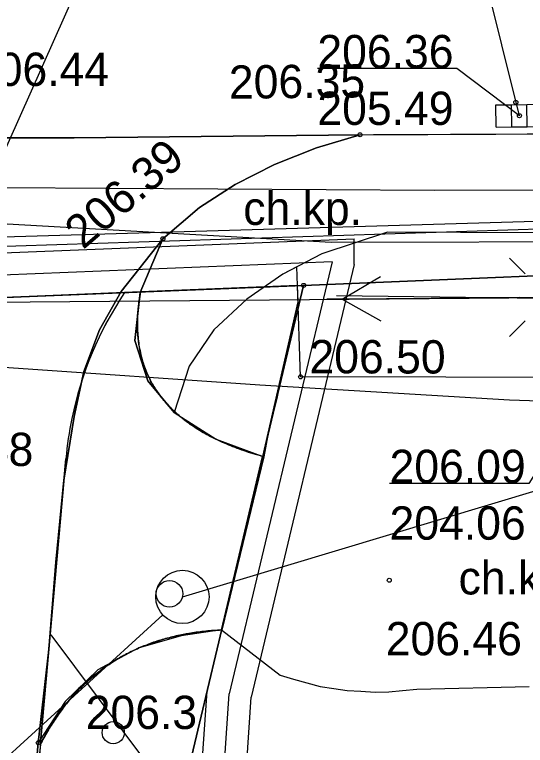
# Model space of a CAD drawing. Extents: x 6512606 to 6513347, y 6022524 to 6022728.
# Drawn here: x 6512739 to 6512750.51, y 6022662.97 to 6022679.43 of the extents above; entities that cross this region are included whole.
import ezdxf

# ---------------------------------------------------------------- set-up
doc = ezdxf.new("R2010")
doc.units = 0
for name, color, linetype in [('20', 7, 'Continuous'), ('203-punkt graniczny', 7, 'Continuous'), ('216-obręb ewidencyjny', 7, 'Continuous'), ('218-kontur użytku gruntowego', 7, 'Continuous'), ('219-działka ewidencyjna', 7, 'Continuous'), ('4', 7, 'Continuous'), ('chodnik', 7, 'Continuous'), ('chodnik (powierzchnia)', 7, 'Continuous'), ('chodnik (powierzchnia)-Atr17', 7, 'Continuous'), ('chodnik-Atr17', 7, 'Continuous'), ('Default', 7, 'Continuous'), ('inny obiekt zagospodarowania terenu', 7, 'Continuous'), ('jezdnia (powierzchnia)', 7, 'Continuous'), ('kolor_chodnik', 7, 'Continuous'), ('kolor_kostka_bet', 7, 'Continuous'), ('kratka ściekowa (punkt)', 7, 'Continuous'), ('krawężnik (linia)', 7, 'Continuous'), ('latarnia na słupie lub maszcie (punkt)', 7, 'Continuous'), ('Level 55', 7, 'Continuous'), ('maxp_kan_deszczowa', 7, 'Continuous'), ('maxp_kraw_nawierzchni', 7, 'Continuous'), ('maxp_krawężnik', 7, 'Continuous'), ('maxp_obrzeże', 7, 'Continuous'), ('maxp_opisy', 7, 'Continuous'), ('maxp_opornik', 7, 'Continuous'), ('maxp_ramka_2', 7, 'Continuous'), ('pikieta naturalna-Atr2', 7, 'Continuous'), ('pikieta sztuczna', 7, 'Continuous'), ('pikieta sztuczna-Atr2', 7, 'Continuous'), ('przewód elektroenergetyczny (linia)', 7, 'Continuous'), ('przewód elektroenergetyczny niskiego napięcia (linia)', 7, 'Continuous'), ('przewód elektroenergetyczny niskiego napięcia (linia) - symbol', 7, 'Continuous'), ('przewód kanalizacyjny (linia)', 7, 'Continuous'), ('przewód wodociągowy (linia)', 7, 'Continuous'), ('punkt o określonej wysokości (sieć kanalizacyjna)', 7, 'Continuous'), ('punkt o określonej wysokości (sieć kanalizacyjna)-Atr2', 7, 'Continuous'), ('punkt o określonej wysokości (sieć kanalizacyjna)-Atr3', 7, 'Continuous'), ('punkt wysokościowy sztuczny', 7, 'Continuous'), ('punkt wysokościowy sztuczny-Atr2', 7, 'Continuous'), ('właz okrągły - siec niezidentyfikowana (punkt)', 7, 'Continuous')]:
    doc.layers.add(name, color=color, linetype=linetype)

# ---------------------------------------------------------------- blocks, each defined once
blk = doc.blocks.new('203')
at = {"layer": 'Default'}
blk.add_circle((0, 0), 0.45, dxfattribs=at)
blk = doc.blocks.new('PE04')
at = {"layer": 'Default'}
for p, q in [((46.5, 0), (37.84, 5)), ((6.5, 0), (0, 0)), ((6.5, 0), (16.5, 0)), ((16.5, 0), (26.5, 0)), ((26.5, 0), (36.5, 0)), ((36.5, 0), (46.5, 0)), ((46.5, 0), (37.84, -5)), ((46.5, 0), (50, 0))]:
    blk.add_line(p, q, dxfattribs=at)
blk = doc.blocks.new('PW02')
at = {"layer": 'Default'}
blk.add_circle((0, 0), 0.45, dxfattribs=at)
blk = doc.blocks.new('PW01')
at = {"layer": 'Default'}
blk.add_circle((0, 0), 0.45, dxfattribs=at)
blk = doc.blocks.new('US05')
at = {"layer": 'Default'}
for p, q in [((-5.25, -2.5), (-5.25, 2.5)), ((-5.25, 2.5), (-1.75, 2.5)), ((-1.75, -2.5), (-1.75, 2.5)), ((-1.75, 2.5), (1.75, 2.5)), ((1.75, -2.5), (1.75, 2.5)), ((1.75, 2.5), (5.25, 2.5)), ((5.25, -2.5), (5.25, 2.5)), ((-5.25, -2.5), (-1.75, -2.5)), ((-1.75, -2.5), (1.75, -2.5)), ((1.75, -2.5), (5.25, -2.5))]:
    blk.add_line(p, q, dxfattribs=at)
blk = doc.blocks.new('SM011')
at = {"layer": 'Default'}
for p, q in [((-5.3, 5.31), (-8.83, 8.84)), ((5.31, 5.31), (8.84, 8.84)), ((-5.3, -5.3), (-8.83, -8.83)), ((5.31, -5.3), (8.84, -8.83))]:
    blk.add_line(p, q, dxfattribs=at)
blk = doc.blocks.new('US22')
at = {"layer": 'Default'}
blk.add_circle((0, 0), 2.5, dxfattribs=at)

msp = doc.modelspace()

# ---------------------------------------------------------------- linework, layer by layer
msp.add_line((6512740.034, 6022615.911), (6512743.337, 6022664.192))
at = {"layer": '20'}
msp.add_line((6512742.779, 6022666.315), (6512753.062, 6022669.403), dxfattribs=at)
at = {"layer": '216-obręb ewidencyjny'}
for points in [[(6512688.62, 6022674.91), (6512702.58, 6022674.18), (6512725.78, 6022672.95), (6512730.35, 6022672.71), (6512735.76, 6022672.94), (6512745.51, 6022673.33), (6512754.87, 6022673.72), (6512768.24, 6022674.27), (6512785.56, 6022674.74), (6512790.49, 6022674.74), (6512796.96, 6022674.74), (6512801.96, 6022670.34), (6512828.67, 6022670.98), (6512833.61, 6022675.02), (6512836.69, 6022675.17), (6512851.94, 6022675.93)], [(6512852.25, 6022608.25), (6512838.47, 6022634.29), (6512825.37, 6022649.66), (6512810.18, 6022663.28), (6512801.96, 6022670.34), (6512796.96, 6022674.74), (6512790.49, 6022674.74), (6512785.56, 6022674.74), (6512768.24, 6022674.27), (6512754.87, 6022673.72), (6512745.51, 6022673.33), (6512735.76, 6022672.94), (6512730.35, 6022672.71), (6512725.78, 6022672.95), (6512702.575, 6022674.177)]]:
    msp.add_lwpolyline(points, dxfattribs=at)
at = {"layer": '218-kontur użytku gruntowego'}
for points in [[(6512754.87, 6022673.72), (6512745.51, 6022673.33)], [(6512745.51, 6022673.33), (6512754.87, 6022673.72)], [(6512745.51, 6022673.33), (6512735.76, 6022672.94)], [(6512735.76, 6022672.94), (6512745.51, 6022673.33)], [(6512745.51, 6022673.33), (6512741.4, 6022656.05)], [(6512741.4, 6022656.05), (6512745.51, 6022673.33)]]:
    msp.add_lwpolyline(points, dxfattribs=at)
at = {"layer": '219-działka ewidencyjna'}
for points in [[(6512754.87, 6022673.72), (6512745.51, 6022673.33)], [(6512745.51, 6022673.33), (6512735.76, 6022672.94)], [(6512745.51, 6022673.33), (6512739.15, 6022646.62)]]:
    msp.add_lwpolyline(points, dxfattribs=at)
at = {"layer": '4'}
for points in [[(6512754.87, 6022673.72), (6512745.51, 6022673.33)], [(6512745.51, 6022673.33), (6512735.76, 6022672.94)], [(6512745.51, 6022673.33), (6512739.15, 6022646.62)]]:
    msp.add_lwpolyline(points, dxfattribs=at)
at = {"layer": 'chodnik'}
msp.add_lwpolyline([(6512755.26, 6022671.25), (6512745.44, 6022671.27), (6512745.37, 6022673.33), (6512745.36, 6022673.75), (6512745.04, 6022673.58), (6512744.23, 6022673.02), (6512743.49, 6022672.33), (6512742.93, 6022671.51), (6512742.59, 6022670.47), (6512743.54, 6022669.87), (6512744.61, 6022669.47), (6512743.66, 6022665.57), (6512744.98, 6022664.55), (6512745.28, 6022664.46), (6512745.58, 6022664.38), (6512745.88, 6022664.3), (6512746.19, 6022664.25), (6512746.49, 6022664.21), (6512746.8, 6022664.19), (6512747.12, 6022664.17), (6512747.43, 6022664.18), (6512747.74, 6022664.21), (6512748.06, 6022664.24), (6512750.59, 6022664.3)], dxfattribs=at)
at = {"layer": 'chodnik (powierzchnia)'}
for points in [[(6512747.08, 6022676.73), (6512757.48, 6022676.77), (6512761.81, 6022676.79), (6512762.96, 6022675.7), (6512762.9, 6022674.52), (6512757.26, 6022674.48), (6512747.4, 6022674.53)], [(6512747.4, 6022674.53), (6512745.92, 6022674.04), (6512745.04, 6022673.58), (6512744.23, 6022673.02), (6512743.49, 6022672.33), (6512742.93, 6022671.51), (6512742.59, 6022670.47), (6512742, 6022671.18), (6512741.71, 6022672.09), (6512741.83, 6022673.17), (6512742.34, 6022674.38), (6512743.16, 6022675.08), (6512743.97, 6022675.6), (6512744.85, 6022676.05), (6512745.8, 6022676.43), (6512746.78, 6022676.72)]]:
    msp.add_lwpolyline(points, dxfattribs=at)
at = {"layer": 'inny obiekt zagospodarowania terenu'}
msp.add_lwpolyline([(6512746.25, 6022673.1), (6512762.53, 6022672.89)], dxfattribs=at)
at = {"layer": 'jezdnia (powierzchnia)'}
for points in [[(6512707.08, 6022677.87), (6512714.85, 6022677.5), (6512727.62, 6022676.91), (6512733.49, 6022676.74), (6512737.49, 6022676.65), (6512740.34, 6022676.65), (6512746.78, 6022676.72), (6512757.48, 6022676.77)], [(6512738.82, 6022655.07), (6512739.53, 6022663.03), (6512739.77, 6022665.13), (6512739.93, 6022667.1), (6512740.11, 6022668.94), (6512740.34, 6022670.38), (6512740.56, 6022671.39), (6512740.91, 6022672.33), (6512741.4, 6022673.19), (6512742.34, 6022674.38), (6512743.16, 6022675.08), (6512743.97, 6022675.6), (6512744.85, 6022676.05), (6512745.8, 6022676.43), (6512746.78, 6022676.72), (6512740.34, 6022676.65), (6512737.49, 6022676.65), (6512733.49, 6022676.74), (6512727.62, 6022676.91)]]:
    msp.add_lwpolyline(points, dxfattribs=at)
at = {"layer": 'kolor_chodnik'}
for p, q in [((6512745.386, 6022672.962), (6512745.371, 6022673.323)), ((6512744.593, 6022669.478), (6512745.386, 6022672.962))]:
    msp.add_line(p, q, dxfattribs=at)
for points in [[(6512745.371, 6022673.323), (6512744.736, 6022673.298), (6512741.877, 6022673.185)], [(6512741.877, 6022673.185), (6512741.835, 6022673.183), (6512741.835, 6022673.183), (6512741.835, 6022673.183)], [(6512744.584, 6022669.48), (6512744.593, 6022669.478)]]:
    msp.add_lwpolyline(points, dxfattribs=at)
for points in [[(6512741.835, 6022673.183), (6512741.559, 6022671.673), (6512742.384, 6022670.713)], [(6512742.384, 6022670.713), (6512743.086, 6022669.897), (6512744.584, 6022669.48)]]:
    msp.add_open_spline(points, degree=2, dxfattribs=at)
at = {"layer": 'kolor_kostka_bet'}
for p, q in [((6512743.337, 6022664.192), (6512745.51, 6022673.33)), ((6512745.51, 6022673.33), (6512744.735, 6022673.299)), ((6512741.477, 6022673.169), (6512732.281, 6022672.792)), ((6512741.835, 6022673.183), (6512741.477, 6022673.169)), ((6512739.584, 6022663.043), (6512740.153, 6022669.425)), ((6512740.153, 6022669.425), (6512739.584, 6022663.043)), ((6512743.66, 6022665.57), (6512744.584, 6022669.48)), ((6512743.337, 6022664.192), (6512743.664, 6022665.569)), ((6512740.868, 6022628.114), (6512743.337, 6022664.192))]:
    msp.add_line(p, q, dxfattribs=at)
for points in [[(6512741.475, 6022673.166), (6512741.477, 6022673.169)], [(6512741.477, 6022673.169), (6512741.475, 6022673.166)], [(6512743.664, 6022665.569), (6512743.66, 6022665.57)]]:
    msp.add_lwpolyline(points, dxfattribs=at)
for centre, radius, start, end in [((6512748.122, 6022668.714), 8, 146.1851, 168.3163), ((6512748.122, 6022668.714), 8, 146.1851, 168.3163), ((6512748.122, 6022668.714), 8, 146.1604, 146.1612), ((6512748.122, 6022668.714), 8, 168.3163, 174.9005), ((6512748.122, 6022668.714), 8, 168.3163, 174.9005), ((6512789.386, 6022658.599), 50, 174.9005, 182.076), ((6512789.386, 6022658.599), 50, 174.9607, 182.076), ((6512789.386, 6022658.599), 50, 174.9005, 174.9607)]:
    msp.add_arc(centre, radius, start, end, dxfattribs=at)
for points in [[(6512744.584, 6022669.48), (6512741.324, 6022670.389), (6512741.835, 6022673.183)], [(6512743.66, 6022665.57), (6512740.824, 6022665.438), (6512739.579, 6022662.991)], [(6512739.579, 6022662.991), (6512740.824, 6022665.438), (6512743.66, 6022665.57)]]:
    msp.add_open_spline(points, degree=2, dxfattribs=at)
at = {"layer": 'krawężnik (linia)'}
for points in [[(6512707.08, 6022677.87), (6512714.85, 6022677.5), (6512727.62, 6022676.91), (6512733.49, 6022676.74), (6512737.49, 6022676.65), (6512740.34, 6022676.65), (6512746.78, 6022676.72), (6512757.48, 6022676.77)], [(6512727.62, 6022676.91), (6512733.49, 6022676.74), (6512737.49, 6022676.65), (6512740.34, 6022676.65), (6512746.78, 6022676.72), (6512745.8, 6022676.43), (6512744.85, 6022676.05), (6512743.97, 6022675.6), (6512743.16, 6022675.08), (6512742.34, 6022674.38), (6512741.4, 6022673.19), (6512740.91, 6022672.33), (6512740.56, 6022671.39), (6512740.34, 6022670.38), (6512740.11, 6022668.94), (6512739.93, 6022667.1), (6512739.77, 6022665.13), (6512739.53, 6022663.03), (6512738.82, 6022655.07)]]:
    msp.add_lwpolyline(points, dxfattribs=at)
msp.add_lwpolyline([(6512742.34, 6022674.38), (6512741.83, 6022673.17), (6512741.71, 6022672.09), (6512742, 6022671.18), (6512742.59, 6022670.47), (6512743.54, 6022669.87), (6512744.61, 6022669.47), (6512743.66, 6022665.57), (6512742.75, 6022665.44), (6512741.78, 6022665.16), (6512740.87, 6022664.67), (6512740.14, 6022663.96), (6512739.53, 6022663.03), (6512739.77, 6022665.13), (6512739.93, 6022667.1), (6512740.11, 6022668.94), (6512740.34, 6022670.38), (6512740.56, 6022671.39), (6512740.91, 6022672.33), (6512741.4, 6022673.19)], close=True, dxfattribs=at)
at = {"layer": 'Level 55'}
msp.add_circle((6512742.487, 6022666.385), 0.3, dxfattribs=at)
at = {"layer": 'maxp_kan_deszczowa'}
msp.add_line((6512742.335, 6022665.911), (6512733.933, 6022658.237), dxfattribs=at)
msp.add_lwpolyline([(6512737.272, 6022673), (6512743.067, 6022673.232), (6512744.735, 6022673.298), (6512744.735, 6022673.299), (6512745.51, 6022673.33), (6512745.121, 6022671.797), (6512744.995, 6022671.244), (6512744.995, 6022671.244), (6512744.904, 6022670.782), (6512744.783, 6022670.312), (6512744.702, 6022669.957), (6512744.61, 6022669.47), (6512743.664, 6022665.567), (6512742.862, 6022665.481), (6512742.368, 6022665.367), (6512741.808, 6022665.168), (6512741.414, 6022664.974), (6512741.058, 6022664.75), (6512740.441, 6022664.252), (6512739.918, 6022663.622), (6512739.581, 6022663.017), (6512739.565, 6022662.833)], dxfattribs=at)
msp.add_circle((6512742.779, 6022666.315), 0.6, dxfattribs=at)
at = {"layer": 'maxp_kraw_nawierzchni'}
for p, q in [((6512745.371, 6022673.323), (6512741.835, 6022673.183)), ((6512732.281, 6022672.792), (6512741.477, 6022673.169)), ((6512741.477, 6022673.169), (6512744.735, 6022673.299)), ((6512741.477, 6022673.169), (6512741.835, 6022673.183))]:
    msp.add_line(p, q, dxfattribs=at)
at = {"layer": 'maxp_krawężnik'}
msp.add_arc((6512789.386, 6022658.599), 50, 174.9005, 182.076, dxfattribs=at)
msp.add_open_spline([(6512739.579, 6022662.991), (6512740.824, 6022665.438), (6512743.66, 6022665.57)], degree=2, dxfattribs=at)
at = {"layer": 'maxp_obrzeże'}
for p, q in [((6512745.386, 6022672.962), (6512745.371, 6022673.323)), ((6512744.592, 6022669.471), (6512745.386, 6022672.962))]:
    msp.add_line(p, q, dxfattribs=at)
at = {"layer": 'maxp_opisy'}
msp.add_line((6512739.811, 6022665.462), (6512747.991, 6022654.543), dxfattribs=at)
msp.add_lwpolyline([(6512737.272, 6022673), (6512753.512, 6022709.396), (6512783.273, 6022709.39)], dxfattribs=at)
at = {"layer": 'maxp_opornik'}
for p, q in [((6512739.584, 6022663.043), (6512740.153, 6022669.425)), ((6512743.66, 6022665.57), (6512744.61, 6022669.47))]:
    msp.add_line(p, q, dxfattribs=at)
for start, end in [(146.1604, 168.3163), (168.3163, 174.9005)]:
    msp.add_arc((6512748.122, 6022668.714), 8, start, end, dxfattribs=at)
msp.add_open_spline([(6512744.584, 6022669.48), (6512741.324, 6022670.389), (6512741.835, 6022673.183)], degree=2, dxfattribs=at)
at = {"layer": 'maxp_ramka_2'}
for p, q in [((6512746.649, 6022673.797), (6512746.649, 6022674.376)), ((6512746.149, 6022673.856), (6512743.834, 6022664.131)), ((6512746.649, 6022673.797), (6512744.33, 6022664.055)), ((6512740.266, 6022611.979), (6512743.834, 6022664.131)), ((6512740.778, 6022612.146), (6512744.33, 6022664.055))]:
    msp.add_line(p, q, dxfattribs=at)
for points in [[(6512723.981, 6022674.046), (6512730.355, 6022673.711), (6512735.719, 6022673.939), (6512746.649, 6022674.376)], [(6512746.149, 6022673.856), (6512735.739, 6022673.44), (6512730.352, 6022673.211), (6512724.475, 6022673.519)]]:
    msp.add_lwpolyline(points, dxfattribs=at)
at = {"layer": 'przewód elektroenergetyczny (linia)'}
for points in [[(6512731.37, 6022676.71), (6512731.37, 6022675.58), (6512748.46, 6022675.47), (6512780.13, 6022675.56), (6512787.87, 6022675.5)], [(6512702.569, 6022673.878), (6512710.28, 6022673.25), (6512716.66, 6022675.97), (6512746.13, 6022674.3), (6512752.79, 6022674.32), (6512760.61, 6022675.35), (6512763.38, 6022676.06), (6512798.79, 6022676.04), (6512803.06, 6022673.02), (6512807.84, 6022668.96), (6512815.24, 6022662.53), (6512819.98, 6022657.77), (6512831.6, 6022645.79), (6512834.59, 6022642.25), (6512837.06, 6022638.75), (6512840.02, 6022634.13), (6512842.26, 6022630.04), (6512846.03, 6022621.35), (6512846.58, 6022618.9), (6512847.6, 6022616.23), (6512852.12, 6022605.09)], [(6512702.603, 6022675.567), (6512731.84, 6022674.22), (6512765.79, 6022675.22), (6512787.87, 6022675.5)]]:
    msp.add_lwpolyline(points, dxfattribs=at)
at = {"layer": 'przewód elektroenergetyczny niskiego napięcia (linia)'}
msp.add_lwpolyline([(6512719.56, 6022672.79), (6512751.03, 6022673.06)], dxfattribs=at)
at = {"layer": 'przewód kanalizacyjny (linia)'}
for points in [[(6512750.37, 6022677.15), (6512748.79, 6022683.52)], [(6512716.83, 6022672.25), (6512720.83, 6022672.11), (6512730.47, 6022671.7), (6512737.04, 6022671.58), (6512738.87, 6022671.48), (6512744.52, 6022671.09), (6512750.15, 6022670.75), (6512752.63, 6022670.67), (6512753.2, 6022670.48)]]:
    msp.add_lwpolyline(points, dxfattribs=at)
at = {"layer": 'przewód wodociągowy (linia)'}
msp.add_lwpolyline([(6512702.579, 6022674.359), (6512731.63, 6022673.98), (6512765.81, 6022675.09), (6512780.05, 6022675.09), (6512787.64, 6022675.26)], dxfattribs=at)
at = {"layer": 'punkt o określonej wysokości (sieć kanalizacyjna)-Atr2'}
for points in [[(6512750.37, 6022677.15), (6512748.96, 6022678.21), (6512745.819, 6022678.21)], [(6512752.3, 6022671.6), (6512750.58, 6022668.87), (6512747.445, 6022668.87)]]:
    msp.add_lwpolyline(points, dxfattribs=at)

# ---------------------------------------------------------------- block references
at = {"layer": '203-punkt graniczny', "xscale": 0.1, "yscale": 0.10000000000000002}
msp.add_blockref('203', (6512745.51, 6022673.33), dxfattribs=at)
at = {"layer": 'kratka ściekowa (punkt)', "xscale": 0.10000000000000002, "yscale": 0.09999999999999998, "rotation": 0.807}
msp.add_blockref('US05', (6512750.37, 6022677.15), dxfattribs=at)
at = {"layer": 'latarnia na słupie lub maszcie (punkt)', "xscale": 0.1, "yscale": 0.10000000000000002}
msp.add_blockref('SM011', (6512751.03, 6022673.06), dxfattribs=at)
at = {"layer": 'pikieta sztuczna', "xscale": 0.1, "yscale": 0.10000000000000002}
msp.add_blockref('PW01', (6512747.44, 6022666.69), dxfattribs=at)
at = {"layer": 'przewód elektroenergetyczny niskiego napięcia (linia) - symbol', "xscale": 0.1, "yscale": 0.10000000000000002, "rotation": -179.50800000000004}
msp.add_blockref('PE04', (6512751.03, 6022673.06), dxfattribs=at)
at = {"layer": 'punkt o określonej wysokości (sieć kanalizacyjna)'}
for p, xscale, yscale, rotation in [((6512750.29, 6022677.45), 0.1, 0.10000000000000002, -75.265), ((6512750.37, 6022677.15), 0.10000000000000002, 0.09999999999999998, 0.807)]:
    msp.add_blockref('PW01', p, dxfattribs=dict(at, xscale=xscale, yscale=yscale, rotation=rotation))
at = {"layer": 'punkt wysokościowy sztuczny', "xscale": 0.1, "yscale": 0.10000000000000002}
for p in [(6512746.78, 6022676.72), (6512742.34, 6022674.38), (6512745.44, 6022671.27), (6512739.53, 6022663.03)]:
    msp.add_blockref('PW02', p, dxfattribs=at)
at = {"layer": 'właz okrągły - siec niezidentyfikowana (punkt)', "xscale": 0.1, "yscale": 0.10000000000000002}
msp.add_blockref('US22', (6512741.22, 6022663.26), dxfattribs=at)

# ---------------------------------------------------------------- texts
at = {"layer": 'chodnik (powierzchnia)-Atr17'}
msp.add_text('ch.kp.', height=0.75, dxfattribs=at).set_placement((6512744.15, 6022674.69))
at = {"layer": 'chodnik-Atr17'}
msp.add_text('ch.kb.', height=0.75, dxfattribs=at).set_placement((6512749, 6022666.37))
at = {"layer": 'pikieta naturalna-Atr2'}
msp.add_text('206.3', height=0.75, dxfattribs=at).set_placement((6512740.6, 6022663.34))
at = {"layer": 'pikieta sztuczna-Atr2'}
msp.add_text('206.46', height=0.75, dxfattribs=at).set_placement((6512747.36, 6022665))
at = {"layer": 'punkt o określonej wysokości (sieć kanalizacyjna)-Atr2'}
for s, p in [('206.36', (6512745.819, 6022678.218)), ('206.09', (6512747.445, 6022668.878))]:
    msp.add_text(s, height=0.75, dxfattribs=at).set_placement(p)
at = {"layer": 'punkt o określonej wysokości (sieć kanalizacyjna)-Atr3'}
for s, p in [('205.49', (6512745.819, 6022676.942)), ('204.06', (6512747.445, 6022667.603))]:
    msp.add_text(s, height=0.75, dxfattribs=at).set_placement(p)
at = {"layer": 'punkt wysokościowy sztuczny-Atr2'}
msp.add_text('206.44', height=0.75, dxfattribs=at).set_placement((6512738.06, 6022677.82))
for s, rotation, p in [('206.35', 0.622, (6512743.83, 6022677.53)), ('206.39', 40.486, (6512740.54, 6022674.12)), ('206.50', 359.883, (6512745.64, 6022671.35)), ('206.48', 359.428, (6512736.35, 6022669.29))]:
    msp.add_text(s, height=0.75, rotation=rotation, dxfattribs=at).set_placement(p)

doc.saveas('drawing.dxf')
